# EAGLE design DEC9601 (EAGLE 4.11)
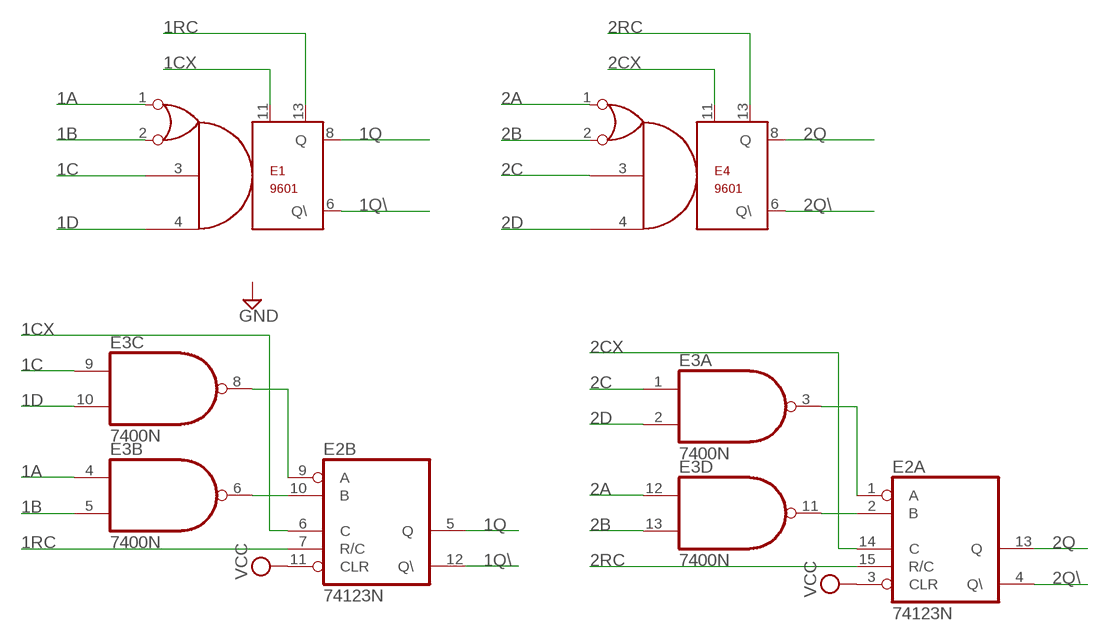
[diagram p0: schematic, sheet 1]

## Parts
E1  9601  [DIL14]
E2  74123N  [DIL16]
E3  7400N  [DIL14]
E4  9601  [DIL14]

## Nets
1A: E1.1 E3.4(B:I0)
1B: E1.2 E3.5(B:I1)
1C: E1.3 E3.9(C:I0)
1CX: E1.11 E2.6(B:C)
1D: E1.4 E3.10(C:I1)
1Q: E1.8(Q) E2.5(B:Q)
1Q\: E1.6(Q\) E2.12(B:Q\)
1RC: E1.13 E2.7(B:R/C)
2A: E3.12(D:I0) E4.1
2B: E3.13(D:I1) E4.2
2C: E3.1(A:I0) E4.3
2CX: E2.14(A:C) E4.11
2D: E3.2(A:I1) E4.4
2Q: E2.13(A:Q) E4.8(Q)
2Q\: E2.4(A:Q\) E4.6(Q\)
2RC: E2.15(A:R/C) E4.13
N$4: E2.10(B:B) E3.6(B:O)
N$6: E2.9(B:A) E3.8(C:O)
N$7: E2.1(A:A) E3.3(A:O)
N$8: E2.2(A:B) E3.11(D:O)
VCC [power]: E2.3(A:CLR) E2.11(B:CLR)

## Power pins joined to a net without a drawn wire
GND: E1.7(GND) E2.8(P:GND) E3.7(P:GND) E4.7(GND)
VCC: E1.14(VCC) E2.16(P:VCC) E3.14(P:VCC) E4.14(VCC)

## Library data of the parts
E1 E4 = dec-con:9601
E2 = 74xx-us:74*123: Retriggerable monostable MULTIVIBRATOR
E3 = 74xx-us:74*00: Quad 2-input NAND gate

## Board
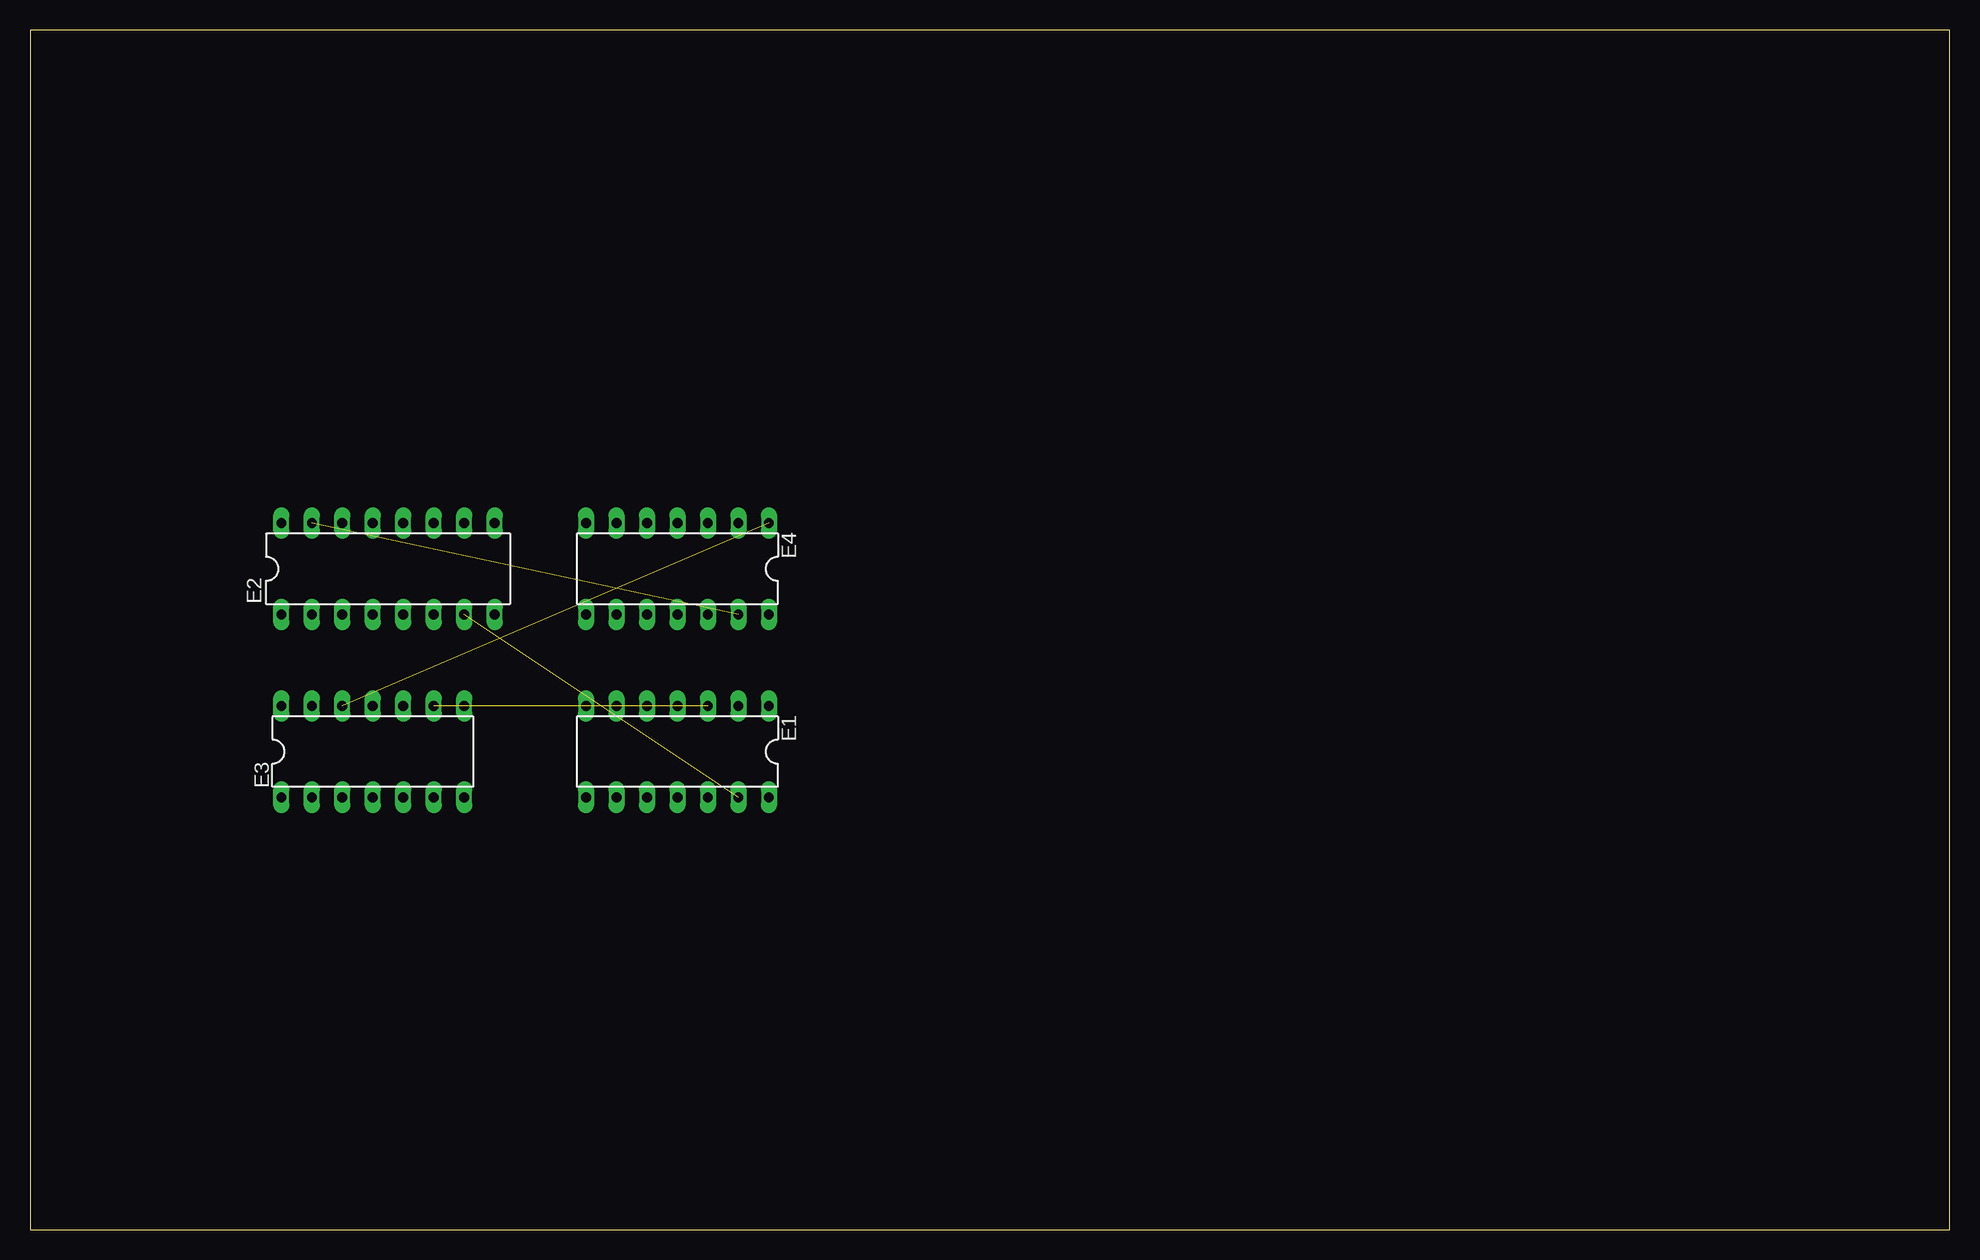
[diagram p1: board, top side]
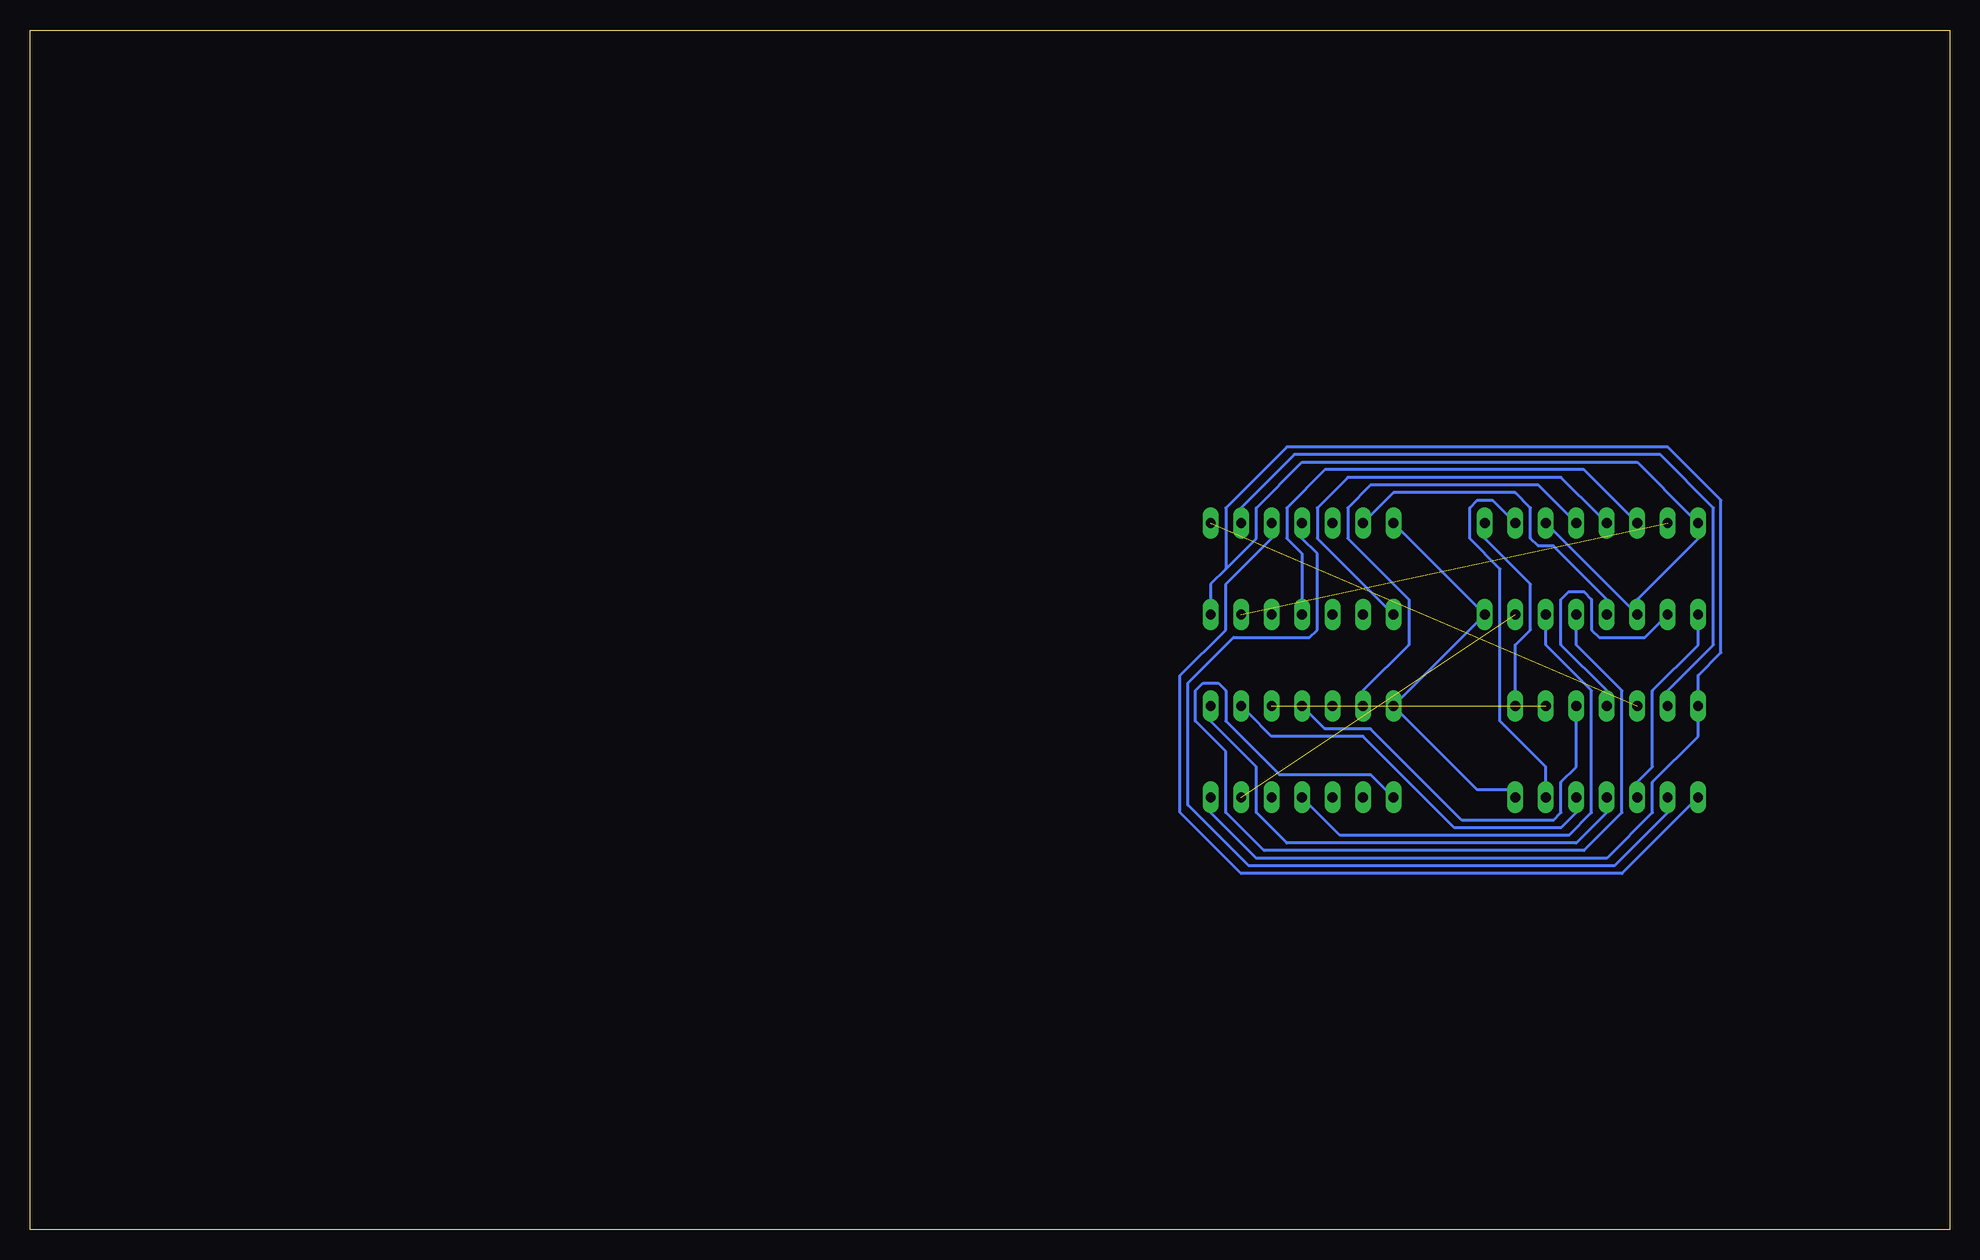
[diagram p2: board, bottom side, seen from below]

Size 160 x 100 mm. Coordinates in mm from the lower left corner, seen from the top.
Outline: 0,0 160,0 160,100 0,100 0,0
Copper layers (1*16): Top 0.035mm / dielectric 1.5mm / Bottom 0.035mm
Design rules "olimex10mil": minimum track width 10mil, minimum drill 24mil, track to track 10mil, track to pad 10mil, pad to pad 10mil, via to via 10mil, smd to smd 10mil, copper to edge 40mil, drill to drill 10mil, minimum pad ring 10mil, minimum via ring 8mil, stop-mask expansion 0mil, vias tented up to drill 0mil, thermal gap 10mil

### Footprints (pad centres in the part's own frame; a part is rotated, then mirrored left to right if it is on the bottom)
DIL14 = drill 0.813 long: 1 -7.62,-3.81; 2 -5.08,-3.81; 3 -2.54,-3.81; 4 0,-3.81; 5 2.54,-3.81; 6 5.08,-3.81; 7 7.62,-3.81; 8 7.62,3.81; 9 5.08,3.81; 10 2.54,3.81; 11 0,3.81; 12 -2.54,3.81; 13 -5.08,3.81; 14 -7.62,3.81
DIL16 = drill 0.813 long: 1 -8.89,-3.81; 2 -6.35,-3.81; 3 -3.81,-3.81; 4 -1.27,-3.81; 5 1.27,-3.81; 6 3.81,-3.81; 7 6.35,-3.81; 8 8.89,-3.81; 9 8.89,3.81; 10 6.35,3.81; 11 3.81,3.81; 12 1.27,3.81; 13 -1.27,3.81; 14 -3.81,3.81; 15 -6.35,3.81; 16 -8.89,3.81

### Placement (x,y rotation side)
E1  53.97,39.84 180 top
E2  29.84,55.08 0 top
E3  28.57,39.84 0 top
E4  53.97,55.08 180 top

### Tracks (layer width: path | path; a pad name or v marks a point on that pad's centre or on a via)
1A
  Bottom 0.254: E3.4 28.57,34.76 31.11,32.22 55.24,32.22 57.78,34.76 57.78,38.57 61.59,42.38 E1.1
1B
  Bottom 0.254: E3.5 31.11,34.76 32.38,33.49 41.27,33.49 48.89,41.11 56.51,41.11 58.41,43.02 E1.2
1C  (1 unrouted)
1CX
  Bottom 0.254: E2.6 33.65,50 33.65,48.73 29.84,44.92 29.84,34.76 31.74,32.85 50.8,32.85 53.34,35.39 E1.11
1D
  Bottom 0.254: E3.10 31.11,42.38 31.11,38.57 32.38,37.3 32.38,34.76 33.02,34.12 40.64,34.12 48.26,41.74 52.07,41.74 53.34,43.02 E1.4
1Q
  Bottom 0.254: E2.5 31.11,50 31.11,48.73 27.3,44.92 27.3,34.76 30.47,31.58 57.15,31.58 60.32,34.76 60.32,39.84 62.86,42.38 62.86,44.92 62.23,45.55 60.96,45.55 60.32,44.92 60.32,42.38 55.88,37.94 48.26,37.94 46.98,36.66 E1.8
1Q\
  Bottom 0.254: E2.12 31.74,59.52 34.29,62.06 48.26,62.06 50.16,60.16 50.16,57.62 45.08,52.54 45.08,48.73 48.89,44.92 E1.6
1RC  (1 unrouted)
2A  (1 unrouted)
2B
  Bottom 0.254: E3.13 23.49,44.92 19.68,48.73 19.68,60.16 24.12,64.61 54.61,64.61 59.05,60.16 E4.2
2C
  Bottom 0.254: E3.1 21.58,35.39 27.3,29.68 59.05,29.68 64.13,34.76 64.13,46.19 60.32,50 60.32,53.81 56.51,57.62 E4.3
2CX
  Bottom 0.254: E4.11 53.97,52.54 53.97,56.35 55.24,57.62 55.24,60.16 52.07,63.34 30.47,63.34 26.66,59.52 E2.14
2D
  Bottom 0.254: E3.2 23.49,34.76 27.93,30.31 58.41,30.31 63.5,35.39 63.5,45.55 59.69,49.37 53.34,49.37 52.7,50 52.7,56.35 53.97,57.62 E4.4
2Q
  Bottom 0.254: E2.13 29.2,59.52 32.38,62.7 50.16,62.7 52.7,60.16 52.7,57.62 46.98,51.91 E4.8
2Q\
  Bottom 0.254: E2.4 28.57,52.54 33.02,56.98 34.29,56.98 34.92,57.62 34.92,60.16 36.19,61.43 46.35,61.43 48.26,59.52 E4.6
2RC  (1 unrouted)
GND
  Bottom 0.254: E3.7 36.83,36.66 39.37,36.66 45.72,43.02 E1.7 45.72,44.28 39.37,50.63 E2.8 39.37,51.91 45.72,58.25 E4.7
N$4
  Bottom 0.254: E3.6 33.65,37.3 33.65,38.57 37.46,42.38 37.46,55.08 40,57.62 40,60.16 39.37,60.8 38.1,60.8 36.83,59.52 E2.10
N$6
  Bottom 0.254: E3.8 36.19,44.92 36.19,48.73 34.92,50 34.92,53.81 38.73,57.62 E2.9
N$7
  Bottom 0.254: E2.1 20.95,50 20.95,48.73 24.76,44.92 24.76,38.57 26.03,37.3 E3.3
N$8
  Bottom 0.254: E3.11 28.57,44.92 32.38,48.73 32.38,52.54 31.74,53.17 30.47,53.17 29.84,52.54 29.84,50 29.2,49.37 25.39,49.37 24.12,50.63 E2.2
VCC
  Bottom 0.254: E1.14 61.59,34.76 57.78,30.95 28.57,30.95 24.76,34.76 24.76,37.3 20.95,41.11 20.95,42.38 E3.14 20.95,44.92 20.95,46.19 19.04,48.09 19.04,60.8 23.49,65.24 55.24,65.24 60.32,60.16 60.32,55.08 | 60.32,55.08 57.78,57.62 57.78,60.16 53.97,63.97 26.03,63.97 21.58,59.52 E2.16 20.95,57.62 26.03,52.54 E2.3 26.66,51.91 33.02,58.25 E2.11 | 60.32,55.08 61.59,53.81 61.59,52.54 E4.14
